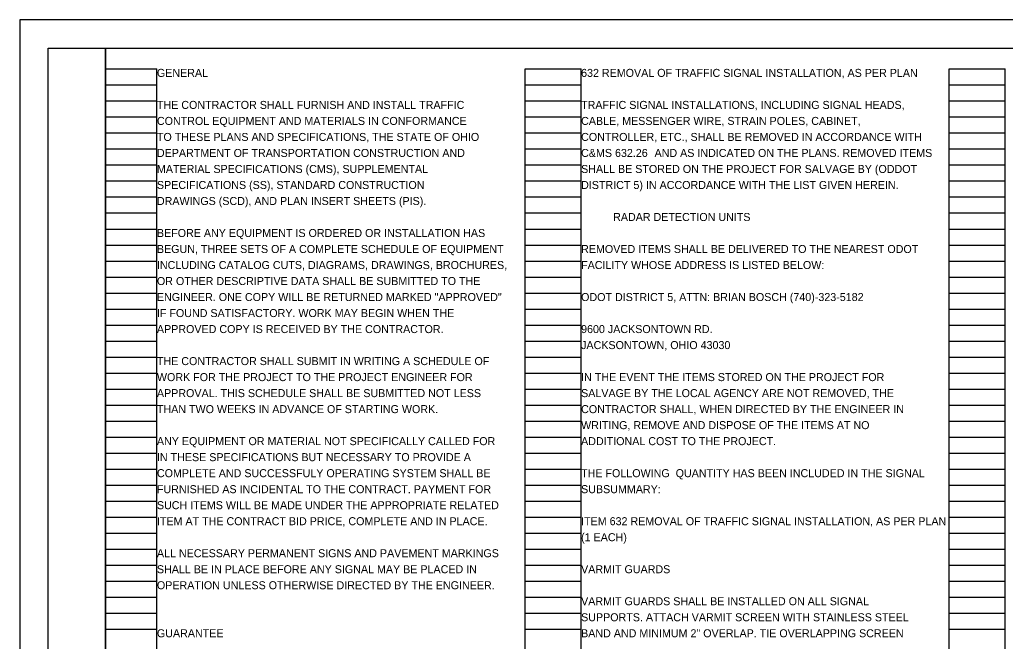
# Model space of a CAD drawing. Extents: x 0 to 34, y 0 to 22.
# Drawn here: x 0 to 17.24, y 11.13 to 22 of the extents above; entities that cross this region are included whole.
import ezdxf

# ---------------------------------------------------------------- set-up
doc = ezdxf.new("R2010")
doc.units = 0
for name, color, linetype in [('SH_Border', 7, 'Continuous'), ('SH_Cut_Line', 7, 'Continuous'), ('SH_Data', 7, 'Continuous'), ('SH_Text', 7, 'Continuous')]:
    doc.layers.add(name, color=color, linetype=linetype)

msp = doc.modelspace()

# ---------------------------------------------------------------- linework, layer by layer
at = {"layer": 'SH_Border'}
for points in [[(0.5, 21.5), (1.5, 21.5), (1.5, 0.5), (0.5, 0.5)], [(1.5, 21.5), (33.5, 21.5), (33.5, 0.5), (1.5, 0.5)]]:
    msp.add_lwpolyline(points, close=True, dxfattribs=at)
at = {"layer": 'SH_Cut_Line'}
msp.add_lwpolyline([(0, 0), (34, 0), (34, 22), (0, 22)], close=True, dxfattribs=at)
at = {"layer": 'SH_Data'}
for p, q in [((1.5, 0.98), (1.5, 21.14)), ((1.5, 21.14), (2.4, 21.14)), ((2.4, 0.98), (2.4, 21.14)), ((8.84, 0.98), (8.84, 21.14)), ((8.84, 21.14), (9.82, 21.14)), ((9.82, 0.98), (9.82, 21.14)), ((16.26, 0.98), (16.26, 21.14)), ((16.26, 21.14), (17.24, 21.14)), ((17.24, 0.98), (17.24, 21.14)), ((1.5, 20.86), (2.4, 20.86)), ((8.84, 20.86), (9.82, 20.86)), ((16.26, 20.86), (17.24, 20.86)), ((1.5, 20.58), (2.4, 20.58)), ((8.84, 20.58), (9.82, 20.58)), ((16.26, 20.58), (17.24, 20.58)), ((1.5, 20.3), (2.4, 20.3)), ((8.84, 20.3), (9.82, 20.3)), ((16.26, 20.3), (17.24, 20.3)), ((1.5, 20.02), (2.4, 20.02)), ((8.84, 20.02), (9.82, 20.02)), ((16.26, 20.02), (17.24, 20.02)), ((1.5, 19.74), (2.4, 19.74)), ((8.84, 19.74), (9.82, 19.74)), ((16.26, 19.74), (17.24, 19.74)), ((1.5, 19.46), (2.4, 19.46)), ((8.84, 19.46), (9.82, 19.46)), ((16.26, 19.46), (17.24, 19.46)), ((1.5, 19.18), (2.4, 19.18)), ((8.84, 19.18), (9.82, 19.18)), ((16.26, 19.18), (17.24, 19.18)), ((1.5, 18.9), (2.4, 18.9)), ((8.84, 18.9), (9.82, 18.9)), ((16.26, 18.9), (17.24, 18.9)), ((1.5, 18.62), (2.4, 18.62)), ((8.84, 18.62), (9.82, 18.62)), ((16.26, 18.62), (17.24, 18.62)), ((1.5, 18.34), (2.4, 18.34)), ((8.84, 18.34), (9.82, 18.34)), ((16.26, 18.34), (17.24, 18.34)), ((1.5, 18.06), (2.4, 18.06)), ((8.84, 18.06), (9.82, 18.06)), ((16.26, 18.06), (17.24, 18.06)), ((1.5, 17.78), (2.4, 17.78)), ((8.84, 17.78), (9.82, 17.78)), ((16.26, 17.78), (17.24, 17.78)), ((1.5, 17.5), (2.4, 17.5)), ((8.84, 17.5), (9.82, 17.5)), ((16.26, 17.5), (17.24, 17.5)), ((1.5, 17.22), (2.4, 17.22)), ((8.84, 17.22), (9.82, 17.22)), ((16.26, 17.22), (17.24, 17.22)), ((1.5, 16.94), (2.4, 16.94)), ((8.84, 16.94), (9.82, 16.94)), ((16.26, 16.94), (17.24, 16.94)), ((1.5, 16.66), (2.4, 16.66)), ((8.84, 16.66), (9.82, 16.66)), ((16.26, 16.66), (17.24, 16.66)), ((1.5, 16.38), (2.4, 16.38)), ((8.84, 16.38), (9.82, 16.38)), ((16.26, 16.38), (17.24, 16.38)), ((1.5, 16.1), (2.4, 16.1)), ((8.84, 16.1), (9.82, 16.1)), ((16.26, 16.1), (17.24, 16.1)), ((1.5, 15.82), (2.4, 15.82)), ((8.84, 15.82), (9.82, 15.82)), ((16.26, 15.82), (17.24, 15.82)), ((1.5, 15.54), (2.4, 15.54)), ((8.84, 15.54), (9.82, 15.54)), ((16.26, 15.54), (17.24, 15.54)), ((1.5, 15.26), (2.4, 15.26)), ((8.84, 15.26), (9.82, 15.26)), ((16.26, 15.26), (17.24, 15.26)), ((1.5, 14.98), (2.4, 14.98)), ((8.84, 14.98), (9.82, 14.98)), ((16.26, 14.98), (17.24, 14.98)), ((1.5, 14.7), (2.4, 14.7)), ((8.84, 14.7), (9.82, 14.7)), ((16.26, 14.7), (17.24, 14.7)), ((1.5, 14.42), (2.4, 14.42)), ((8.84, 14.42), (9.82, 14.42)), ((16.26, 14.42), (17.24, 14.42)), ((1.5, 14.14), (2.4, 14.14)), ((8.84, 14.14), (9.82, 14.14)), ((16.26, 14.14), (17.24, 14.14)), ((1.5, 13.86), (2.4, 13.86)), ((8.84, 13.86), (9.82, 13.86)), ((16.26, 13.86), (17.24, 13.86)), ((1.5, 13.58), (2.4, 13.58)), ((8.84, 13.58), (9.82, 13.58)), ((16.26, 13.58), (17.24, 13.58)), ((1.5, 13.3), (2.4, 13.3)), ((8.84, 13.3), (9.82, 13.3)), ((16.26, 13.3), (17.24, 13.3)), ((1.5, 13.02), (2.4, 13.02)), ((8.84, 13.02), (9.82, 13.02)), ((16.26, 13.02), (17.24, 13.02)), ((1.5, 12.74), (2.4, 12.74)), ((8.84, 12.74), (9.82, 12.74)), ((16.26, 12.74), (17.24, 12.74)), ((1.5, 12.46), (2.4, 12.46)), ((8.84, 12.46), (9.82, 12.46)), ((16.26, 12.46), (17.24, 12.46)), ((1.5, 12.18), (2.4, 12.18)), ((8.84, 12.18), (9.82, 12.18)), ((16.26, 12.18), (17.24, 12.18)), ((1.5, 11.9), (2.4, 11.9)), ((8.84, 11.9), (9.82, 11.9)), ((16.26, 11.9), (17.24, 11.9)), ((1.5, 11.62), (2.4, 11.62)), ((8.84, 11.62), (9.82, 11.62)), ((16.26, 11.62), (17.24, 11.62)), ((1.5, 11.34), (2.4, 11.34)), ((8.84, 11.34), (9.82, 11.34)), ((16.26, 11.34), (17.24, 11.34))]:
    msp.add_line(p, q, dxfattribs=at)

# ---------------------------------------------------------------- texts
at = {"layer": 'SH_Text'}
for s, p in [('GENERAL', (2.4, 21)), ('632 REMOVAL OF TRAFFIC SIGNAL INSTALLATION, AS PER PLAN', (9.82, 21)), ('THE CONTRACTOR SHALL FURNISH AND INSTALL TRAFFIC', (2.4, 20.44)), ('TRAFFIC SIGNAL INSTALLATIONS, INCLUDING SIGNAL HEADS,', (9.82, 20.44)), ('CONTROL EQUIPMENT AND MATERIALS IN CONFORMANCE', (2.4, 20.16)), ('CABLE, MESSENGER WIRE, STRAIN POLES, CABINET,', (9.82, 20.16)), ('TO THESE PLANS AND SPECIFICATIONS, THE STATE OF OHIO', (2.4, 19.88)), ('CONTROLLER, ETC., SHALL BE REMOVED IN ACCORDANCE WITH', (9.82, 19.88)), ('DEPARTMENT OF TRANSPORTATION CONSTRUCTION AND', (2.4, 19.6)), ('C&MS 632.26', (9.82, 19.6)), (' AND AS INDICATED ON THE PLANS. REMOVED ITEMS', (11.053, 19.6)), ('MATERIAL SPECIFICATIONS (CMS), SUPPLEMENTAL', (2.4, 19.32)), ('SHALL BE STORED ON THE PROJECT FOR SALVAGE BY (ODDOT', (9.82, 19.32)), ('SPECIFICATIONS (SS), STANDARD CONSTRUCTION', (2.4, 19.04)), ('DISTRICT 5) IN ACCORDANCE WITH THE LIST GIVEN HEREIN.', (9.82, 19.04)), ('DRAWINGS (SCD), AND PLAN INSERT SHEETS (PIS).', (2.4, 18.76)), ('RADAR DETECTION UNITS', (10.38, 18.48)), ('BEFORE ANY EQUIPMENT IS ORDERED OR INSTALLATION HAS', (2.4, 18.2)), ('BEGUN, THREE SETS OF A COMPLETE SCHEDULE OF EQUIPMENT', (2.4, 17.92)), ('REMOVED ITEMS SHALL BE DELIVERED TO THE NEAREST ODOT', (9.82, 17.92)), ('INCLUDING CATALOG CUTS, DIAGRAMS, DRAWINGS, BROCHURES,', (2.4, 17.64)), ('FACILITY WHOSE ADDRESS IS LISTED BELOW:', (9.82, 17.64)), ('OR OTHER DESCRIPTIVE DATA SHALL BE SUBMITTED TO THE', (2.4, 17.36)), ('ENGINEER. ONE COPY WILL BE RETURNED MARKED "APPROVED"', (2.4, 17.08)), ('ODOT DISTRICT 5, ATTN: BRIAN BOSCH (740)-323-5182', (9.82, 17.08)), ('IF FOUND SATISFACTORY. WORK MAY BEGIN WHEN THE', (2.4, 16.8)), ('APPROVED COPY IS RECEIVED BY THE CONTRACTOR.', (2.4, 16.52)), ('9600 JACKSONTOWN RD.', (9.82, 16.52)), ('JACKSONTOWN, OHIO 43030', (9.82, 16.24)), ('THE CONTRACTOR SHALL SUBMIT IN WRITING A SCHEDULE OF', (2.4, 15.96)), ('WORK FOR THE PROJECT TO THE PROJECT ENGINEER FOR', (2.4, 15.68)), ('IN THE EVENT THE ITEMS STORED ON THE PROJECT FOR', (9.82, 15.68)), ('APPROVAL. THIS SCHEDULE SHALL BE SUBMITTED NOT LESS', (2.4, 15.4)), ('SALVAGE BY THE LOCAL AGENCY ARE NOT REMOVED, THE', (9.82, 15.4)), ('THAN TWO WEEKS IN ADVANCE OF STARTING WORK.', (2.4, 15.12)), ('CONTRACTOR SHALL, WHEN DIRECTED BY THE ENGINEER IN', (9.82, 15.12)), ('WRITING, REMOVE AND DISPOSE OF THE ITEMS AT NO', (9.82, 14.84)), ('ANY EQUIPMENT OR MATERIAL NOT SPECIFICALLY CALLED FOR', (2.4, 14.56)), ('ADDITIONAL COST TO THE PROJECT.', (9.82, 14.56)), ('IN THESE SPECIFICATIONS BUT NECESSARY TO PROVIDE A', (2.4, 14.28)), ('COMPLETE AND SUCCESSFULY OPERATING SYSTEM SHALL BE', (2.4, 14)), ('THE FOLLOWING  QUANTITY HAS BEEN INCLUDED IN THE SIGNAL', (9.82, 14)), ('FURNISHED AS INCIDENTAL TO THE CONTRACT. PAYMENT FOR ', (2.4, 13.72)), ('SUBSUMMARY:', (9.82, 13.72)), ('SUCH ITEMS WILL BE MADE UNDER THE APPROPRIATE RELATED', (2.4, 13.44)), ('ITEM AT THE CONTRACT BID PRICE, COMPLETE AND IN PLACE.', (2.4, 13.16)), ('ITEM 632 REMOVAL OF TRAFFIC SIGNAL INSTALLATION, AS PER PLAN', (9.82, 13.16)), ('(1 EACH)', (9.82, 12.88)), ('ALL NECESSARY PERMANENT SIGNS AND PAVEMENT MARKINGS', (2.4, 12.6)), ('SHALL BE IN PLACE BEFORE ANY SIGNAL MAY BE PLACED IN', (2.4, 12.32)), ('VARMIT GUARDS', (9.82, 12.32)), ('OPERATION UNLESS OTHERWISE DIRECTED BY THE ENGINEER.', (2.4, 12.04)), ('VARMIT GUARDS SHALL BE INSTALLED ON ALL SIGNAL', (9.82, 11.76)), ('SUPPORTS. ATTACH VARMIT SCREEN WITH STAINLESS STEEL', (9.82, 11.48)), ('GUARANTEE', (2.4, 11.2)), ('BAND AND MINIMUM 2" OVERLAP. TIE OVERLAPPING SCREEN', (9.82, 11.2))]:
    msp.add_text(s, height=0.14, dxfattribs=at).set_placement(p)

doc.saveas('drawing.dxf')
